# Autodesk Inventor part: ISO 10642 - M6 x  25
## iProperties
Comments: To add or edit properties for Autodesk Inventor files, use iProperties.
Created: 2005-06
Part Number: ISO 10642 - M6 x  25
Vendor: Autodesk Inc.
Document SubType Name: Modeling
Designer: John Blackburn
Material: Default
Description: Hexagon Socket Countersunk Head Screw
Standard: ISO 10642
Alert: To add or edit properties for Autodesk Inventor files, use iProperties.
Control State: 0
Master: False
Checked Out: False
Shininess: 64.0
Length Units: 11269
Angle Units: 11279
Time Units: 11290
Mass Units: 11283
Length Display Precision: 3
Angle Display Precision: 2
Compacted: True
EGR: 1
Density: 0.0
Volumn: 0.0
Area: 0.0
PropertySet Name: Model Information
Author: John Blackburn
Revision Number: 8
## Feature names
1. Body [Revolution]
2. Slot [Extrusion]
3. Chamfer1
